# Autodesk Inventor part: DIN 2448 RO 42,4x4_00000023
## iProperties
Created: 2006-02
Part Number: DIN 2448 RO 42,4x4_00000023
Material: Default
Document SubType Name: Modeling
Designer: FranzK
Stock Number: DIN 2448 RO 42,4x4
Mass: 437.925 g
Surface Area: 2196.64 cm^2
Volume: 437.925 cm^3
Density: 1 g/cm^3
G_L: 894.000 mm
G_W: 42.400 mm
G_H: 42.400 mm
AFG_Item: 42.4 x 4
CSToolsMass: 0.4
CSToolsVolume: 437925.0
CSToolsArea: 2197.0
Author: FranzK
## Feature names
1. AFG_Detailed_DIN 2448 RO 42,4x4_00000023 [Extrusion]
2. AFG_Simplified_DIN 2448 RO 42,4x4_00000023 [Extrusion]
3. Extrusion5
